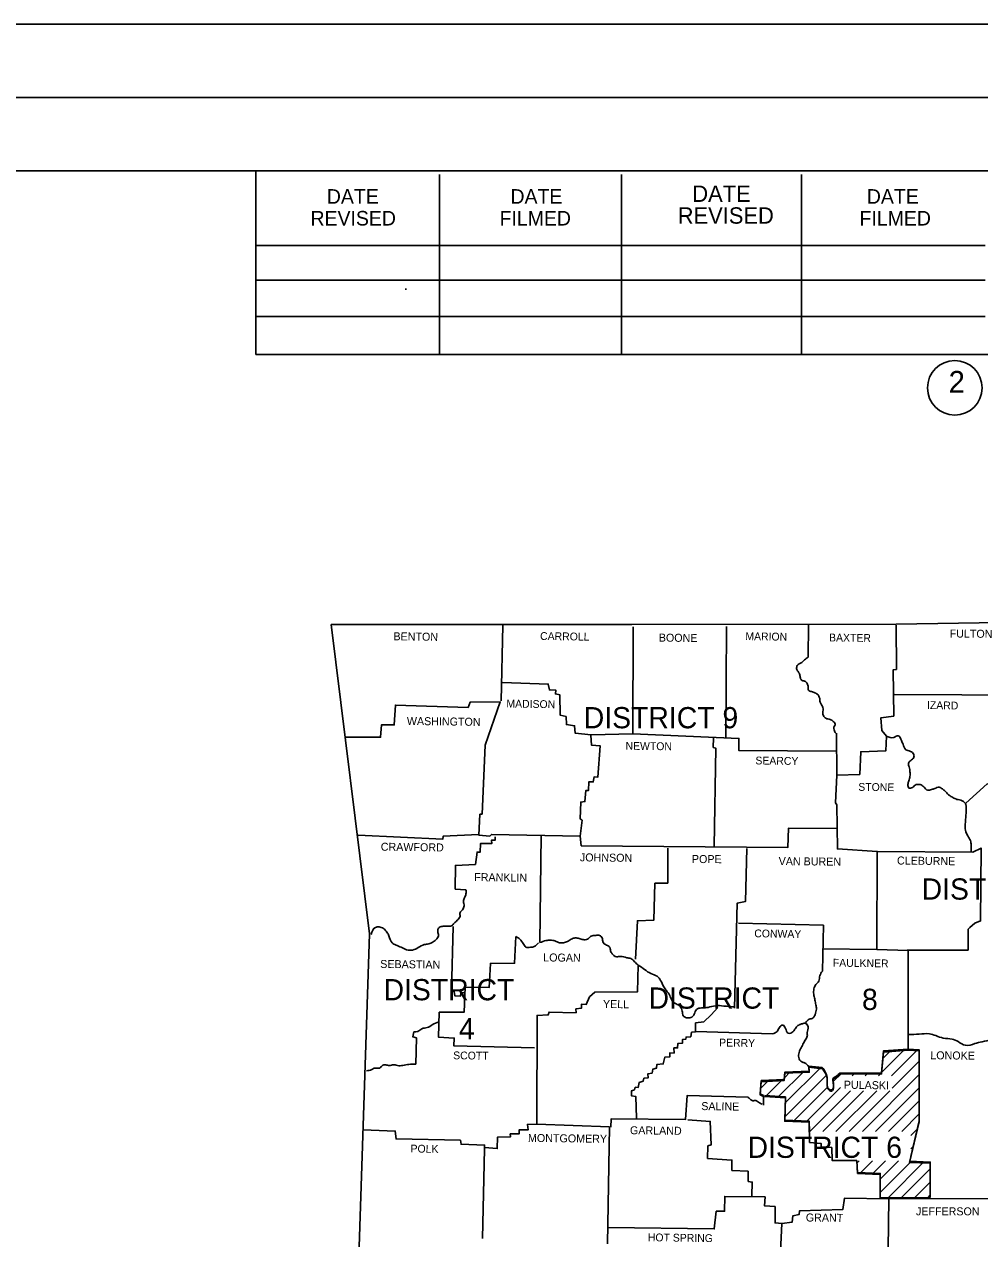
# Model space of a CAD drawing. Extents: x 23481 to 28196, y 1325020 to 1327623.
# Drawn here: x 26099 to 26612, y 1326929 to 1327582 of the extents above; entities that cross this region are included whole.
import ezdxf

# ---------------------------------------------------------------- set-up
doc = ezdxf.new("R2010")
doc.units = 0
doc.layers.add('S_ELECTRIC_UTILITIES_ANNOT', color=7, linetype='Continuous')
doc.layers.add('S_PRIMARY_CTL_ANNOT', color=7, linetype='Continuous')

msp = doc.modelspace()

# ---------------------------------------------------------------- linework, layer by layer
at = {"layer": 'S_ELECTRIC_UTILITIES_ANNOT'}
for p, q in [((27081.89, 1327581.68), (23572.11, 1327581.68)), ((27081.89, 1327542.3), (23808.34, 1327542.3)), ((23883.86, 1327502.83), (27045.67, 1327502.83)), ((26223.04, 1327404.15), (26223.04, 1327502.83)), ((26321.72, 1327404.15), (26321.72, 1327500.88)), ((26419.42, 1327404.15), (26419.42, 1327500.88)), ((26516.14, 1327404.15), (26516.14, 1327500.88)), ((26223.04, 1327462.77), (26614.82, 1327462.77)), ((26223.04, 1327444.21), (26614.82, 1327444.21)), ((26303.94, 1327439.28), (26303.21, 1327439.28)), ((26223.04, 1327404.15), (26223.04, 1327424.67)), ((26223.04, 1327424.67), (26614.82, 1327424.67)), ((27045.67, 1327404.15), (26223.04, 1327404.15)), ((26413.1, 1326988.98), (26411.93, 1326926.18))]:
    msp.add_line(p, q, dxfattribs=at)
for points in [[(26263.4, 1327259.08), (26425.1, 1327258.98), (26567, 1327259.28), (26734.4, 1327261.88), (26812, 1327263.68)], [(26263.4, 1327259.08), (26284.1, 1327092.88), (26275.1, 1326821.58)], [(26355.7, 1327258.48), (26354.8, 1327217.98)], [(26355.5, 1327227.88), (26380.1, 1327227.08), (26380.7, 1327223.88), (26384.1, 1327223.78), (26384, 1327221.78), (26386.4, 1327221.18), (26386.6, 1327210.28), (26389.7, 1327209.58), (26389.9, 1327205.28), (26394.3, 1327204.68), (26394.5, 1327200.68), (26403.2, 1327199.78), (26425.6, 1327200.28), (26425.8, 1327257.78)], [(26475.9, 1327257.98), (26475.6, 1327198.58)], [(26519.9, 1327258.68), (26519.7, 1327241.58)], [(26567, 1327258.68), (26567.2, 1327234.88), (26565.5, 1327234.78), (26565.8, 1327209.88), (26558.8, 1327208.88), (26559.4, 1327202.18), (26561.8, 1327199.08), (26561.6, 1327191.18), (26548, 1327190.68), (26547.5, 1327178.48), (26535.1, 1327178.08), (26534.5, 1327163.28), (26535.2, 1327162.08), (26535.5, 1327138.48), (26556.9, 1327137.08), (26556.6, 1327084.38), (26573.6, 1327083.88), (26573.6, 1327030.28), (26560.2, 1327029.28), (26559.2, 1327017.48), (26536.7, 1327017.38)], [(26651.7, 1327260.18), (26651.9, 1327235.38), (26638.9, 1327234.68), (26638.5, 1327221.08), (26566.2, 1327221.48)], [(26271.3, 1327198.58), (26290, 1327198.48), (26290.5, 1327205.08), (26297.4, 1327205.08), (26298, 1327215.78), (26337, 1327214.38), (26338.2, 1327217.38), (26354.3, 1327217.48), (26346.2, 1327194.28), (26344.6, 1327157.18), (26343.4, 1327157.08), (26342.8, 1327145.88), (26348.7, 1327145.38), (26349.6, 1327146.28), (26397.3, 1327145.38), (26397.8, 1327140.08)], [(26403, 1327199.58), (26403.4, 1327194.18), (26408, 1327193.88), (26406.8, 1327177.08), (26404.7, 1327177.18), (26404.3, 1327174.48), (26401.9, 1327174.48), (26401.8, 1327169.88), (26400.3, 1327169.78), (26399.8, 1327163.88), (26397.6, 1327163.58), (26397.3, 1327154.58), (26398.3, 1327153.88), (26397.3, 1327145.38)], [(26425.6, 1327200.28), (26482.6, 1327197.88), (26482.5, 1327191.38), (26534.8, 1327190.98)], [(26468.9, 1327198.18), (26468.8, 1327192.98), (26470.1, 1327192.68), (26469.3, 1327139.88)], [(26535.1, 1327178.08), (26535, 1327200.58)], [(26604.5, 1327163.08), (26615.9, 1327173.38), (26651.9, 1327172.88), (26652.6, 1327166.18), (26665.7, 1327166.68)], [(26277.9, 1327145.78), (26323.4, 1327143.68), (26323.6, 1327145.28), (26342.6, 1327146.18)], [(26376.3, 1327145.78), (26375.6, 1327088.08)], [(26397.8, 1327140.08), (26508.8, 1327139.18), (26509.3, 1327149.68), (26535.1, 1327149.38)], [(26351.6, 1327144.98), (26351.6, 1327143.18), (26349.7, 1327143.18), (26349.8, 1327141.38), (26343.7, 1327141.28), (26343.6, 1327136.78), (26341.9, 1327136.78), (26341, 1327130.08), (26330.2, 1327129.58), (26330.1, 1327116.88), (26335.9, 1327116.48)], [(26444.42, 1327138.81), (26444.32, 1327120.11), (26437.42, 1327120.01), (26436.82, 1327100.11), (26428.02, 1327099.81), (26427.02, 1327079.21)], [(26486.78, 1327138.7), (26486.05, 1327110.11), (26481.65, 1327109.37), (26480.18, 1327052.91)], [(26556.9, 1327137.08), (26608.3, 1327136.78), (26612.7, 1327138.88), (26612.4, 1327099.78), (26609.4, 1327098.48), (26606.7, 1327096.18), (26605.8, 1327095.28), (26605.7, 1327084.08), (26573, 1327084.08)], [(26329.1, 1327096.68), (26328.1, 1327062.28), (26329.6, 1327061.88), (26329.9, 1327059.48), (26332.9, 1327059.28), (26333.2, 1327060.98), (26335.6, 1327061.38)], [(26482.3, 1327098.48), (26528, 1327097.38), (26527.4, 1327072.68)], [(26362.7, 1327091.28), (26362, 1327076.98), (26349, 1327076.88), (26348.3, 1327063.88), (26335.4, 1327064.18), (26335, 1327050.78), (26321.5, 1327050.68), (26321.1, 1327037.28), (26329.6, 1327036.78), (26329.3, 1327032.68), (26372.7, 1327031.48)], [(26527.5, 1327084.78), (26556.6, 1327084.38)], [(26428.4, 1327075.98), (26428, 1327061.58), (26405.2, 1327061.48), (26402.2, 1327058.88), (26400.5, 1327054.88), (26398, 1327055.08), (26397.9, 1327052.78), (26395, 1327052.48), (26395.1, 1327050.38), (26380.6, 1327050.78), (26380.1, 1327049.18), (26374.1, 1327048.98), (26373.9, 1326990.62)], [(26471.3, 1327053.18), (26467.7, 1327049.28), (26463.8, 1327045.58), (26459.3, 1327044.88), (26459.3, 1327040.18), (26457.1, 1327039.88), (26456.7, 1327037.48), (26454.2, 1327037.28), (26454, 1327036.18), (26452.3, 1327036.08), (26452.2, 1327033.98), (26449.8, 1327033.88), (26449.6, 1327031.48), (26447.6, 1327031.48), (26447.7, 1327028.68), (26445.5, 1327028.88), (26445.4, 1327026.68), (26442.7, 1327026.48), (26441.9, 1327022.88), (26438.5, 1327022.58), (26438.2, 1327020.58), (26436.4, 1327020.08), (26435.9, 1327017.98), (26433.6, 1327017.48), (26433.8, 1327015.38), (26431.5, 1327015.18), (26431.1, 1327013.58), (26429, 1327012.98), (26428.5, 1327010.28), (26426.9, 1327010.38), (26426.4, 1327008.98), (26424.9, 1327008.48), (26424.8, 1327005.78), (26427.1, 1327005.38), (26427.5, 1326993.78)], [(26309, 1327022.78), (26309.3, 1327036.88), (26307.3, 1327037.48), (26307.9, 1327040.18)], [(26500.6, 1327038.98), (26459.4, 1327040.28)], [(26536.7, 1327017.98), (26559.2, 1327018.08), (26560.2, 1327029.88), (26573.6, 1327030.88)], [(26559.2, 1327018.18), (26571.8, 1327030.78)], [(26559.9, 1327025.88), (26564.2, 1327030.18)], [(26564.6, 1327016.48), (26578.6, 1327030.48)], [(26573.6, 1327030.88), (26579.4, 1327030.48), (26579.5, 1326992.28), (26574.9, 1326973.18)], [(26573.6, 1327030.28), (26579.4, 1327029.88), (26579.5, 1326991.68), (26574.3, 1326969.98), (26585.4, 1326969.48), (26585.3, 1326951.08)], [(26495.7, 1327005.88), (26495.7, 1327005.98), (26493.9, 1327006.88), (26494.6, 1327013.88), (26506.9, 1327014.58), (26507.3, 1327018.48), (26520.4, 1327018.98), (26520.1, 1327021.68), (26527.3, 1327020.88)], [(26564.9, 1327009.78), (26579.4, 1327024.28)], [(26527.3, 1327020.28), (26520.1, 1327021.08), (26520.4, 1327018.38), (26507.3, 1327017.88), (26506.9, 1327013.98), (26494.6, 1327013.28), (26493.9, 1327006.28), (26495.7, 1327005.38), (26495.7, 1327000.78)], [(26504.1, 1327005.48), (26517.4, 1327018.78)], [(26507, 1327015.48), (26510.1, 1327018.58)], [(26507.2, 1326994.48), (26529.7, 1327016.88)], [(26507.5, 1327001.88), (26526.5, 1327020.88)], [(26533.2, 1327013.38), (26537.8, 1327017.98)], [(26543.4, 1327016.48), (26544.9, 1327017.98)], [(26548.9, 1326986.58), (26579.4, 1327017.18)], [(26550.5, 1327016.48), (26551.9, 1327017.98)], [(26557.5, 1327016.48), (26559, 1327017.98)], [(26494.2, 1327009.68), (26498.7, 1327014.18)], [(26497.4, 1327005.88), (26506.2, 1327014.68)], [(26512.3, 1326992.48), (26530.4, 1327010.58)], [(26519.1, 1326992.18), (26537.2, 1327010.28)], [(26520.5, 1326986.48), (26520.6, 1326986.58), (26542.5, 1327008.48)], [(26527.6, 1326986.58), (26549.5, 1327008.48)], [(26534.7, 1326986.58), (26556.6, 1327008.48)], [(26541.8, 1326986.58), (26563.7, 1327008.48)], [(26555.9, 1326986.58), (26579.4, 1327010.08)], [(26487.5, 1327004.98), (26454.8, 1327005.98), (26453.9, 1326993.08), (26413.9, 1326993.28), (26413.73, 1326988.95)], [(26520.5, 1326986.58), (26520.3, 1326992.18), (26507.2, 1326992.68), (26507.6, 1327005.18), (26496.4, 1327005.88)], [(26496.4, 1327005.28), (26507.6, 1327004.58), (26507.2, 1326992.08), (26520.3, 1326991.58), (26520.5, 1326980.68), (26526.7, 1326980.18), (26526.7, 1326978.28), (26532.5, 1326977.88), (26532.7, 1326970.88), (26545.9, 1326970.88), (26546.3, 1326963.98), (26558.5, 1326963.38), (26558.4, 1326950.38)], [(26563, 1326986.58), (26579.4, 1327003.08)], [(26570.1, 1326986.58), (26579.4, 1326995.98)], [(26373.9, 1326990.62), (26373.9, 1326990.48), (26368.9, 1326990.38), (26369.3, 1326987.38), (26364.5, 1326987.48), (26364.4, 1326985.28), (26359.7, 1326985.28), (26359.8, 1326983.68), (26352.8, 1326983.48), (26352.7, 1326977.38), (26345.9, 1326977.98)], [(26413.1, 1326988.98), (26373.9, 1326990.48)], [(26455.1, 1326992.88), (26467.2, 1326991.98), (26467.6, 1326979.38), (26465.9, 1326978.78), (26465.7, 1326972.08), (26478.8, 1326971.18), (26478.8, 1326965.68), (26487.5, 1326965.18), (26487.6, 1326959.68), (26489.7, 1326959.38), (26489.6, 1326951.98)], [(26280.6, 1326987.38), (26297.9, 1326986.78), (26298.3, 1326982.58), (26332.9, 1326981.88), (26333.3, 1326979.68), (26345.9, 1326979.28), (26345.8, 1326977.38)], [(26574.9, 1326984.38), (26578.4, 1326987.88)], [(26345.88, 1326977.2), (26344.8, 1326928.98)], [(26574.9, 1326977.28), (26576.2, 1326978.58)], [(26558.4, 1326950.98), (26558.5, 1326963.98), (26546.3, 1326964.58), (26546, 1326970.78)], [(26546.1, 1326969.68), (26547.2, 1326970.78)], [(26548, 1326964.48), (26554.3, 1326970.78)], [(26554.8, 1326964.18), (26561.4, 1326970.78)], [(26558.4, 1326953.78), (26575.2, 1326970.48)], [(26558.5, 1326960.88), (26568.4, 1326970.78)], [(26562.7, 1326950.88), (26582, 1326970.28)], [(26574.4, 1326970.78), (26574.3, 1326970.58), (26585.4, 1326970.08), (26585.3, 1326951.68)], [(26677.7, 1326961.88), (26639.9, 1326962.88), (26639.7, 1326950.58), (26563.2, 1326950.28)], [(26569.8, 1326950.88), (26585.3, 1326966.48)], [(26576.9, 1326950.98), (26585.3, 1326959.38)], [(26412.1, 1326934.98), (26469.3, 1326934.18), (26470.4, 1326943.68), (26474.9, 1326943.68), (26475, 1326951.68), (26496.6, 1326951.38), (26496.4, 1326946.58), (26502, 1326946.18), (26502, 1326937.38), (26505.6, 1326937.08), (26505.55, 1326936.16)], [(26505.6, 1326937.08), (26511.2, 1326937.88), (26511.6, 1326941.28), (26514.9, 1326941.88), (26515.1, 1326943.88), (26538.4, 1326944.58), (26539.3, 1326950.68), (26563.2, 1326950.28)], [(26563.2, 1326950.88), (26558.4, 1326950.98)], [(26563.2, 1326950.28), (26562.6, 1326909.68), (26560.3, 1326909.58), (26560, 1326884.48)], [(26585.3, 1326951.08), (26563.2, 1326950.88)], [(26584, 1326950.98), (26585.3, 1326952.38)], [(26505.6, 1326937.08), (26504.4, 1326910.88), (26503.5, 1326911.18), (26503.6, 1326897.58)]]:
    msp.add_lwpolyline(points, dxfattribs=at)
msp.add_circle((26598.59, 1327386.27), 14.67, dxfattribs=at)
for points in [[(26519.7, 1327241.58), (26517.9, 1327240.08), (26516.3, 1327238.68), (26513.9, 1327236.98), (26513.6, 1327235.38), (26514.4, 1327233.78), (26515.2, 1327232.48), (26515.5, 1327230.68), (26516.2, 1327229.18), (26517.9, 1327228.58), (26519.3, 1327227.28), (26519.8, 1327225.48), (26520, 1327223.78), (26521.6, 1327222.98), (26523.4, 1327222.38), (26525.1, 1327221.18), (26525.9, 1327219.68), (26526.1, 1327217.78), (26526.8, 1327216.28), (26527.6, 1327214.48), (26527.8, 1327212.98), (26527.6, 1327211.48), (26528, 1327210.08), (26529.3, 1327208.68), (26531.6, 1327207.98), (26533.2, 1327206.98), (26534.3, 1327205.58), (26533.6, 1327203.88), (26533.7, 1327202.38), (26534.6, 1327200.58)], [(26561.8, 1327199.08), (26565.8, 1327198.38), (26568.2, 1327199.28), (26569.9, 1327196.68), (26570.8, 1327194.68), (26572.3, 1327191.78), (26574.7, 1327190.88), (26576.5, 1327189.28), (26576.5, 1327187.58), (26574.9, 1327185.98), (26573.7, 1327184.38), (26574.1, 1327182.48), (26574.5, 1327179.88), (26574.5, 1327177.38), (26573.9, 1327175.08), (26573.4, 1327172.98), (26573.9, 1327171.18), (26575.8, 1327171.48), (26577.8, 1327172.98), (26579.9, 1327172.98), (26581.9, 1327171.88), (26584, 1327169.98), (26586.1, 1327170.38), (26587.8, 1327170.88), (26590.2, 1327171.58), (26591.9, 1327170.68), (26593.4, 1327169.48), (26595.2, 1327167.58), (26596.9, 1327166.38), (26599.1, 1327165.28), (26601.8, 1327164.58), (26604.3, 1327162.88), (26604.7, 1327159.98), (26604.6, 1327157.48), (26604.4, 1327154.38), (26604.2, 1327150.98), (26604.5, 1327147.68), (26605.6, 1327145.48), (26607, 1327142.88), (26607.4, 1327140.48), (26607.3, 1327136.68)], [(26335.9, 1327116.48), (26335.9, 1327114.38), (26335.1, 1327112.18), (26334.6, 1327110.28), (26334.9, 1327107.78), (26334, 1327105.78), (26332.7, 1327104.18), (26332.7, 1327102.18), (26331.2, 1327100.08), (26329.6, 1327098.48), (26328.2, 1327097.18), (26325.7, 1327096.98), (26323.6, 1327096.88), (26321.5, 1327096.18), (26320.7, 1327094.68), (26321.1, 1327092.38), (26320.3, 1327090.18), (26318.2, 1327088.48), (26315.9, 1327087.38), (26313.5, 1327086.98), (26310.2, 1327085.38), (26307.2, 1327084.08), (26304, 1327084.28), (26301, 1327085.58), (26298.3, 1327086.78), (26296.2, 1327087.98), (26294.5, 1327091.68), (26293.4, 1327093.68), (26291.5, 1327095.68), (26289.2, 1327096.48), (26287.3, 1327096.28), (26285, 1327092.38)], [(26362.7, 1327091.28), (26364.9, 1327089.88), (26366.6, 1327087.58), (26368.1, 1327085.68), (26370.6, 1327085.58), (26372.6, 1327085.98), (26374.9, 1327087.98)], [(26375.6, 1327088.08), (26378.9, 1327089.18), (26381.3, 1327089.38), (26383.7, 1327088.98), (26386.2, 1327087.98), (26388.9, 1327088.18), (26390.9, 1327088.88), (26392.9, 1327090.18), (26395.1, 1327090.58), (26397.2, 1327090.18), (26399.4, 1327089.58), (26401.8, 1327090.28), (26403.2, 1327091.58), (26405.6, 1327091.98), (26407.7, 1327091.98), (26409.2, 1327090.28), (26409.5, 1327088.48), (26411.4, 1327086.78), (26413.1, 1327085.68), (26413.6, 1327083.58), (26414.5, 1327082.08), (26415.4, 1327081.08), (26416.7, 1327080.48), (26418.9, 1327080.68), (26422.3, 1327079.98), (26424.5, 1327079.48), (26426.5, 1327077.78), (26428.4, 1327075.98)], [(26428.4, 1327075.98), (26431.9, 1327073.58), (26435.2, 1327071.48), (26438.6, 1327069.98), (26440.5, 1327067.78), (26442.2, 1327064.38), (26443.6, 1327062.28), (26445.4, 1327059.68), (26446.7, 1327056.78), (26448.8, 1327055.18), (26451, 1327053.78), (26452.1, 1327051.28), (26452.6, 1327048.78), (26455, 1327047.58), (26457.3, 1327048.08), (26458.6, 1327049.58), (26459.8, 1327052.18), (26462.5, 1327052.98), (26466, 1327053.28), (26470, 1327054.18), (26474.4, 1327053.98), (26480.6, 1327053.58)], [(26527.4, 1327072.68), (26526.1, 1327070.38), (26525.5, 1327067.38), (26523.9, 1327065.48), (26522.9, 1327063.28), (26522.8, 1327060.38), (26523.3, 1327057.78), (26523.8, 1327055.28), (26524.2, 1327052.98), (26523.7, 1327050.08), (26522.4, 1327047.58), (26520.4, 1327046.88), (26518.5, 1327045.18)], [(26307.9, 1327040.18), (26310.1, 1327040.38), (26312.2, 1327041.78), (26315, 1327042.38), (26317.8, 1327043.88), (26321.3, 1327045.48)], [(26500.6, 1327038.98), (26503.1, 1327040.38), (26504.4, 1327042.48), (26506, 1327043.78), (26507.6, 1327041.98), (26509, 1327039.38), (26510.5, 1327039.38), (26512.4, 1327041.18), (26513.6, 1327042.78), (26515.1, 1327043.98), (26516.7, 1327044.48), (26518.4, 1327044.68), (26519.7, 1327042.78), (26519.3, 1327039.78), (26519.3, 1327037.78), (26518.2, 1327035.68), (26517, 1327033.48), (26515.7, 1327030.98), (26514.7, 1327028.28), (26514.9, 1327025.68), (26516.3, 1327023.98), (26517.9, 1327023.48), (26520.1, 1327021.28)], [(26573.8, 1327038.68), (26579.4, 1327038.88), (26584.9, 1327039.08), (26588.4, 1327038.08), (26592.4, 1327036.78), (26597.1, 1327036.18), (26600.4, 1327034.88), (26604.3, 1327032.88), (26609.3, 1327033.78), (26613.2, 1327034.78), (26618.3, 1327036.08), (26621.6, 1327037.48), (26625.4, 1327038.68), (26629.2, 1327038.18), (26633.5, 1327037.38), (26636.2, 1327035.78), (26641.1, 1327036.48), (26641.1, 1327042.68)], [(26309, 1327022.78), (26306.1, 1327022.68), (26302.8, 1327022.28), (26299.8, 1327021.88), (26297.1, 1327022.38), (26294.6, 1327021.98), (26292.9, 1327022.38), (26290.8, 1327021.88), (26289.6, 1327020.68), (26287.1, 1327020.68), (26285.3, 1327019.88), (26282.4, 1327019.18)], [(26527.3, 1327020.88), (26529, 1327018.68), (26530, 1327015.68), (26530, 1327012.28), (26530.8, 1327009.48), (26532.4, 1327008.88), (26533.4, 1327011.28), (26533.2, 1327013.68), (26533.2, 1327015.08), (26534.9, 1327016.28), (26536.7, 1327017.98)], [(26527.3, 1327020.28), (26529, 1327018.08), (26530, 1327015.08), (26530, 1327011.68), (26530.8, 1327008.88), (26532.4, 1327008.28), (26533.4, 1327010.68), (26533.2, 1327013.08), (26533.2, 1327014.48), (26534.9, 1327015.68), (26536.7, 1327017.38)], [(26495, 1327001.28), (26493.1, 1327002.28), (26491.6, 1327003.18), (26490, 1327003.08), (26488.7, 1327003.88), (26487.5, 1327004.98)]]:
    msp.add_spline(points, degree=3, dxfattribs=at)
at = {"layer": 'S_PRIMARY_CTL_ANNOT'}
msp.add_lwpolyline([(23808.34, 1327542.3), (27091.73, 1327542.3), (27091.73, 1325408.97), (23808.34, 1325408.97)], close=True, dxfattribs=at)

# ---------------------------------------------------------------- texts
at = {"layer": 'S_ELECTRIC_UTILITIES_ANNOT'}
for s, height, p in [('DATE', 7.82, (26261.14, 1327485.24)), ('DATE', 7.82, (26359.82, 1327485.24)), ('DATE', 8.793, (26457.52, 1327486.22)), ('DATE', 7.82, (26551.31, 1327485.24)), ('REVISED', 7.82, (26252.35, 1327473.52)), ('FILMED', 7.82, (26353.96, 1327473.52)), ('REVISED', 8.793, (26449.7, 1327474.5)), ('FILMED', 7.82, (26547.4, 1327473.52)), ('2', 11.72, (26595.28, 1327383.64)), ('DISTRICT 9', 11.4, (26399.2, 1327203.28)), ('DISTRICT', 11.4, (26580.75, 1327111.19)), ('DISTRICT', 11.4, (26291.6, 1327057.08)), ('DISTRICT', 11.4, (26434, 1327052.58)), ('8', 11.4, (26548.7, 1327051.88)), ('4', 11.4, (26332.1, 1327036.08)), ('DISTRICT 6', 11.4, (26487.2, 1326972.38)), ('JEFFERSON', 4.3, (26577.7, 1326941.48))]:
    msp.add_text(s, height=height, dxfattribs=at).set_placement(p)
for s, height, rotation, p in [('BENTON', 4.301, 359.25271, (26296.9, 1327250.58)), ('CARROLL', 4.201, 359.14808, (26375.7, 1327250.78)), ('BOONE', 4.301, 359.40007, (26439.5, 1327249.88)), ('MARION', 4.201, 359.18542, (26486, 1327250.68)), ('BAXTER', 4.201, 359.25594, (26531, 1327249.98)), ('FULTON', 4.3, 359.49961, (26595.8, 1327252.08)), ('MADISON', 4.201, 359.09062, (26357.6, 1327214.48)), ('IZARD', 4.199, 358.92583, (26583.6, 1327213.68)), ('WASHINGTON', 4.3, 359.23201, (26304.1, 1327205.08)), ('NEWTON', 4.201, 359.2717, (26421.6, 1327191.78)), ('SEARCY', 4.199, 359.25271, (26491.4, 1327183.88)), ('STONE', 4.199, 359.40007, (26546.7, 1327169.68)), ('CRAWFORD', 4.299, 359.27706, (26290.1, 1327137.48)), ('JOHNSON', 4.301, 359.3514, (26397.1, 1327131.78)), ('POPE', 4.301, 359.61547, (26457.3, 1327130.88)), ('VAN BUREN', 4.301, 359.35078, (26503.9, 1327129.78)), ('CLEBURNE', 4.3, 359.25352, (26567.5, 1327130.08)), ('FRANKLIN', 4.301, 359.18154, (26340.3, 1327121.18)), ('CONWAY', 4.199, 359.03714, (26490.8, 1327090.98)), ('LOGAN', 4.301, 359.39691, (26377.4, 1327077.98)), ('SEBASTIAN', 4.299, 359.28159, (26289.8, 1327074.48)), ('FAULKNER', 4.201, 359.24862, (26533, 1327075.18)), ('YELL', 4.301, 359.19871, (26409.5, 1327052.98)), ('PERRY', 4.2, 359.08578, (26471.9, 1327032.28)), ('SCOTT', 4.201, 359.40628, (26329, 1327025.38)), ('LONOKE', 4.301, 359.49742, (26585.4, 1327025.38)), ('PULASKI', 4.301, 359.05305, (26538.9, 1327009.58)), ('SALINE', 4.301, 359.14914, (26462.3, 1326998.08)), ('GARLAND', 4.301, 359.36576, (26424, 1326985.08)), ('MONTGOMERY', 4.301, 359.29442, (26369.2, 1326980.98)), ('POLK', 4.199, 359.21518, (26306.1, 1326975.28)), ('GRANT', 4.301, 359.40319, (26518.5, 1326938.18)), ('HOT SPRING', 4.201, 359.22157, (26433.6, 1326927.58))]:
    msp.add_text(s, height=height, rotation=rotation, dxfattribs=at).set_placement(p)

doc.saveas('drawing.dxf')
